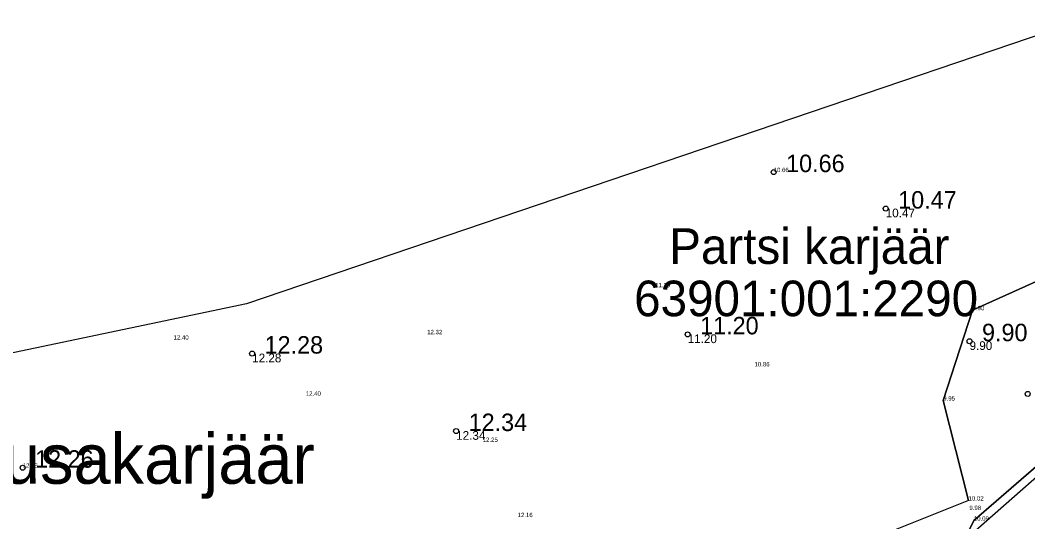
# Model space of a CAD drawing. Extents: x 433497 to 434382, y 6534486 to 6534993.
# Drawn here: x 433673.1 to 433753.8, y 6534854.6 to 6534894.8 of the extents above; entities that cross this region are included whole.
import ezdxf

# ---------------------------------------------------------------- set-up
doc = ezdxf.new("R2010")
doc.units = 0
for name, color, linetype in [('kataster', 7, 'Continuous'), ('KORGUS-EH2000', 7, 'Continuous'), ('MOOTKORG-EH2000', 7, 'Continuous'), ('RELJEEF', 7, 'Continuous'), ('VEEKOGU', 7, 'Continuous'), ('VORMISTUS', 7, 'Continuous')]:
    doc.layers.add(name, color=color, linetype=linetype)

msp = doc.modelspace()

# ---------------------------------------------------------------- linework, layer by layer
at = {"layer": 'KORGUS-EH2000'}
for centre in [(433733.444, 6534882.634), (433742.42, 6534879.715), (433726.556, 6534869.643), (433749.136, 6534869.093), (433691.666, 6534868.102), (433753.795, 6534864.874), (433708.011, 6534861.9), (433673.284, 6534858.966)]:
    msp.add_circle(centre, 0.2, dxfattribs=at)
at = {"layer": 'RELJEEF'}
msp.add_line((433746.039, 6534855.111), (433746.039, 6534855.111), dxfattribs=at)
msp.add_lwpolyline([(433749.058, 6534856.332), (433741.841, 6534853.465), (433717.91, 6534845.411), (433702.328, 6534840.514), (433691.755, 6534835.121), (433679.525, 6534829.764), (433651.528, 6534818.64), (433637.327, 6534811.851), (433630.595, 6534812.126), (433622.045, 6534814.376), (433614.685, 6534815.117), (433605.841, 6534812.999), (433591.428, 6534809.544), (433575.413, 6534803.952), (433570.231, 6534802.507)], dxfattribs=at)
at = {"layer": 'VEEKOGU'}
msp.add_line((433748.765, 6534853.283), (433749.479, 6534854.726), dxfattribs=at)
for points in [[(433917.357, 6534901.473), (433910.646, 6534903.91), (433905.733, 6534906.185), (433897.201, 6534904.664), (433864.652, 6534892.255), (433840.997, 6534882.39), (433822.758, 6534877.106), (433813.338, 6534872.69), (433806.812, 6534870.137), (433792.733, 6534866.126), (433778.163, 6534862.151), (433760.314, 6534861.045), (433757.652, 6534861.824), (433749.479, 6534854.726), (433748.765, 6534853.283)], [(433749.479, 6534854.726), (433757.652, 6534861.824), (433760.314, 6534861.045), (433778.163, 6534862.151), (433792.733, 6534866.126), (433806.812, 6534870.137), (433813.338, 6534872.69), (433822.758, 6534877.106), (433840.997, 6534882.39), (433864.652, 6534892.255), (433897.201, 6534904.664), (433905.733, 6534906.185), (433910.646, 6534903.91), (433917.357, 6534901.473)], [(433749.058, 6534856.332), (433747.031, 6534864.341), (433749.381, 6534871.575), (433758.754, 6534875.81), (433762.133, 6534877.256), (433760.546, 6534888.872), (433759.609, 6534893.801), (433762.728, 6534893.927)], [(433762.728, 6534893.927), (433759.609, 6534893.801), (433760.546, 6534888.872), (433762.133, 6534877.256), (433758.754, 6534875.81), (433749.381, 6534871.575), (433747.031, 6534864.341), (433749.058, 6534856.332)], [(433822.217, 6534876.48), (433821.93, 6534876.376), (433813.446, 6534872.233), (433806.595, 6534869.831), (433792.716, 6534865.968), (433778.125, 6534861.85), (433760.219, 6534860.83), (433757.827, 6534861.154), (433749.641, 6534853.939)], [(433749.058, 6534856.332), (433741.841, 6534853.465), (433722.771, 6534845.253), (433710.509, 6534841.204), (433704.412, 6534838.967), (433698.912, 6534836.045), (433689.963, 6534831.852), (433681.025, 6534828.643), (433674.289, 6534826.026), (433651.647, 6534816.525), (433637.528, 6534810.175), (433630.797, 6534811.068), (433623.412, 6534812.9), (433613.311, 6534813.674), (433591.338, 6534808.449), (433572.407, 6534802.271)]]:
    msp.add_lwpolyline(points, dxfattribs=at)
at = {"layer": 'VORMISTUS'}
msp.add_lwpolyline([(433756.833, 6534894.348), (433691.203, 6534872.087), (433653.508, 6534864.187), (433636.546, 6534862.392), (433627.673, 6534847.824), (433564.128, 6534829.695), (433582.608, 6534768.478), (433587.883, 6534751.004), (433591.763, 6534747.472), (433594.096, 6534737.418), (433589.968, 6534732.121), (433592.57, 6534706.447), (433596.133, 6534671.303), (433599.93, 6534613.558), (433630.448, 6534534.937), (433664.149, 6534549.227), (433704.536, 6534572.568), (433752.081, 6534596.222), (433789.501, 6534614.839)], dxfattribs=at)
msp.add_lwpolyline([(433756.833, 6534894.348), (433691.203, 6534872.087), (433653.508, 6534864.187), (433636.546, 6534862.392), (433627.673, 6534847.824), (433564.128, 6534829.695), (433582.608, 6534768.478), (433587.883, 6534751.004), (433591.763, 6534747.472), (433594.096, 6534737.418), (433589.968, 6534732.121), (433592.57, 6534706.447), (433596.133, 6534671.303), (433599.93, 6534613.558), (433630.448, 6534534.937), (433664.149, 6534549.227), (433704.536, 6534572.568), (433752.081, 6534596.222), (433789.501, 6534614.839)], dxfattribs=at)

# ---------------------------------------------------------------- texts
at = {"layer": 'kataster'}
for s, p in [('Partsi karjäär', (433725.08, 6534875.287)), ('63901:001:2290', (433722.269, 6534871.096))]:
    msp.add_text(s, height=2.85, dxfattribs=at).set_placement(p)
at = {"layer": 'KORGUS-EH2000'}
for s, p in [('10.66', (433734.444, 6534882.634)), ('10.47', (433743.42, 6534879.715)), ('11.20', (433727.556, 6534869.643)), ('9.90', (433750.136, 6534869.093)), ('12.28', (433692.666, 6534868.102)), ('12.34', (433709.011, 6534861.9)), ('12.26', (433674.284, 6534858.966))]:
    msp.add_text(s, height=1.4, dxfattribs=at).set_placement(p)
at = {"layer": 'MOOTKORG-EH2000'}
for s, height, p in [('10.66', 0.35, (433733.444, 6534882.634)), ('10.47', 0.7, (433742.42, 6534879.015)), ('11.29', 0.35, (433723.954, 6534873.413)), ('9.90', 0.35, (433749.381, 6534871.575)), ('12.32', 0.35, (433705.687, 6534869.655)), ('12.40', 0.35, (433685.372, 6534869.224)), ('11.20', 0.7, (433726.556, 6534868.943)), ('9.90', 0.7, (433749.136, 6534868.393)), ('12.28', 0.7, (433691.666, 6534867.402)), ('10.86', 0.35, (433731.911, 6534867.078)), ('12.40', 0.35, (433695.963, 6534864.732)), ('9.95', 0.35, (433747.031, 6534864.341)), ('12.34', 0.7, (433708.011, 6534861.2)), ('12.25', 0.35, (433710.138, 6534861.032)), ('12.26', 0.35, (433673.284, 6534858.966)), ('10.02', 0.35, (433749.058, 6534856.332)), ('9.98', 0.35, (433749.124, 6534855.579)), ('12.16', 0.35, (433712.932, 6534855.007)), ('10.09', 0.35, (433749.479, 6534854.726))]:
    msp.add_text(s, height=height, dxfattribs=at).set_placement(p)
at = {"layer": 'VORMISTUS'}
msp.add_text('Partsi 2 kruusakarjäär', height=4, dxfattribs=at).set_placement((433644.658, 6534857.68))

doc.saveas('drawing.dxf')
